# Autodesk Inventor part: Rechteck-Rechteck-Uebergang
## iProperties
Created: 2005-05
Part Number: Rechteck-Rechteck-Uebergang
Material: .
Document SubType Name: Blech
Designer: rsc
Manufacturer: Standard
Standards Organization: Custom
Kanten: brechen
Oberflächen: Ra 3,2
Radien: 2
Toleranzen: ISO 2768 - m
Author: rsc
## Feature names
1. Erhebung2
2. Rundung1 [Fillet]
3. Wandstärke1
4. Extrusion1
5. ExtrusionAbwicklung1
